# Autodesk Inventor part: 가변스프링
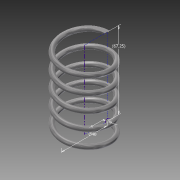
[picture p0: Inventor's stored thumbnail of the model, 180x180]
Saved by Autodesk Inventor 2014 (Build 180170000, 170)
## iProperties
Created: 2017-01
Part Number: 가변스프링
Material: Stainless Steel
Document SubType Name: Modeling
Designer: user
Density: 1 g/cm^3
Appearance: Semi-Polished
Mass: 7.7967 g
Surface Area: 78.9807 cm^2
Volume: 7.7967 cm^3
Author: user
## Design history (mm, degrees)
sketch "Sketch1"
  geometry: L1 (0, 0)-(20, 0); L2 (20, 0)-(20, 67.25); L3 (20, 67.25)-(0, 67.25); L4 (0, 67.25)-(0, 0); C1 r 2 at (20, 0)
  constraints: 8 end point, 2 parallel, 1 centre point, 1 coincident, 1 horizontal, 1 perpendicular
  dimensions: "d0" = 40 diameter of L2 L4; "d1" = 67.25 distance between parallel lines of L3 L1 (derived); "d2" = 4 diameter of C1
coil "Coil1" pitch "d3" = 10; turns "d5" = 5; dims "d4" = 67.25 (= d1), "d6" = 0, angle "d7" = 90 deg, angle "d8" = 90 deg, "d9" = 0, "d10" = 0
sketch "Sketch2"
  geometry: L1 (0, 18)-(0, 22) reference; 1 further point
  constraints: 1 vertical alignment
extrude "Extrusion1" cut sketch "Sketch2" distance "d11" = 10; taper "d12" = 0 deg
workplane "Work Plane1"
sketch "Sketch3"
  geometry: L1 (0, 18)-(0, 22) reference; 1 further point
  constraints: 1 vertical alignment
extrude "Extrusion2" cut sketch "Sketch3" distance "d13" = 10; taper "d14" = 0 deg
body "Solid1"
node "Project Cut Edges1"
node "Project Cut Edges2"
